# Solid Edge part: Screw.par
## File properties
Title: Screw
Author: Deepak Maini
Template: Normal.par
Last saved by: Robert a Rhodes jr
Revision: 5
Application: Solid Edge
Material: aluminum
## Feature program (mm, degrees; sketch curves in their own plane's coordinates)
sketch for "unnamed Protrusion 1" plane through (0, 0, 0) normal (0, -1, 0) x-axis (1, 0, 0)
  circle centre (0, 0) radius 12.5
extrude "unnamed Protrusion 1" add finite 25 along +normal
sketch for "unnamed Protrusion 2" plane through (0, -25, 0) normal (0, -1, 0) x-axis (1, 0, 0)
  circle centre (0, 0) radius 10
extrude "unnamed Protrusion 2" add finite 96 along +normal
sketch for "unnamed Protrusion 3" plane through (0, -121, 0) normal (0, -1, 0) x-axis (1, 0, 0)
  circle centre (0, 0) radius 6
extrude "unnamed Protrusion 3" add finite 4 along +normal
sketch for "unnamed Protrusion 4" plane through (0, -125, 0) normal (0, -1, 0) x-axis (1, 0, 0)
  circle centre (0, 0) radius 4
extrude "unnamed Protrusion 4" add finite 6 along +normal
sketch for "unnamed RevolvedProtrusion 1" plane through (0, 0, 0) normal (0, 0, 1) x-axis (1, 0, 0)
  line (0, -131) -> (6, -131)
  line (6, -131) -> (6, -141)
  line (6, -141) -> (0, -143.8522)
  line (0, -143.8522) -> (0, -131)
revolve "unnamed RevolvedProtrusion 1" add full turn 360 deg about sketch line (0, -131) -> (0, -106.3065)
sketch for "unnamed Cutout 1" plane through (0, 0, 0) normal (1, 0, 0) x-axis (0, 1, 0)
  circle centre (-13, 0) radius 5.5
extrude "unnamed Cutout 1" cut finite 222.1 symmetric
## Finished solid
Body 1: solid body, 12 faces, 12 edges, 1 vertex.
  Faces by surface: cylinder 6, plane 5, cone 1
  Edges by curve: circle 10, intersection 2
Bounding box of the edges (mm): 25.000 x 141.000 x 25.000, from (-12.5, -141, -12.5) to (12.5, 0, 12.5).
Cylindrical faces by radius (mm): R4 x1, R5.5 x1, R6 x2, R10 x1, R12.5 x1
Conical faces (half-angle, radius in mm at the cone's reference point): 64.5754 deg R6 x1
Planar faces by outward normal: +y 2, -y 3
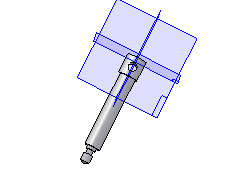
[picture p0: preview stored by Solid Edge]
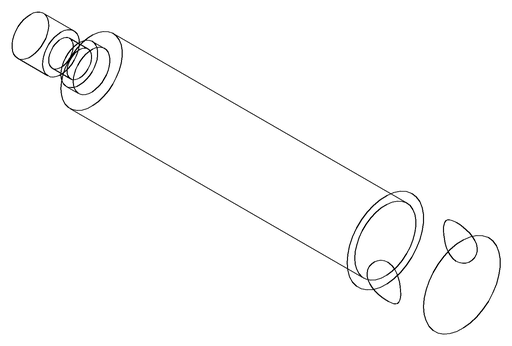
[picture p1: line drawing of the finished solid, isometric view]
